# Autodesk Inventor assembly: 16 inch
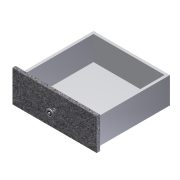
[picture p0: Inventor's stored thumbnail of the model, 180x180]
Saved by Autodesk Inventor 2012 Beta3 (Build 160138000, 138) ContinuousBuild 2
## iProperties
Created: 2011-02
Part Number: 16 inch
Document SubType Name: Assembly
Designer: Beta-8540w
Author: Beta-8540w
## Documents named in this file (12)
- C:\Inventor 2012 Essentials\Assemblies\Chapter 15\c15-04\c15-04-03.iam
- C:\Inventor 2012 Essentials\Parts\Chapter 15\c15-11.ipt
- C:\Inventor 2012 Essentials\Parts\Chapter 15\c15-12.ipt
- C:\Inventor 2012 Essentials\Parts\Chapter 15\c15-13.ipt
- C:\Inventor 2012 Essentials\Parts\Chapter 15\c15-15.ipt
- C:\Inventor 2012 Essentials\Parts\Chapter 15\c15-17.ipt
- C:\Inventor 2012 Essentials\Content Center Files\en-US\ANSI B18.6.3(28)\ANSI B18.6.3 - 8-36 UNF - 0.875(12).ipt
- C:\Inventor 2012 Essentials\Assemblies\Chapter 15\c15-04.iam
- C:\Inventor 2012 Essentials\Parts\Chapter 15\c15-11\c15-11-03.ipt
- C:\Inventor 2012 Essentials\Parts\Chapter 15\c15-12\c15-12-03.ipt
- C:\Inventor 2012 Essentials\Parts\Chapter 15\c15-13\c15-13-03.ipt
- C:\Inventor 2012 Essentials\Parts\Chapter 15\c15-15\c15-15-03.ipt
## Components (7 placed, 6 different names)
1. c15-11-03:1 — Mate:1, Flush:1, Mate:2, Mate:6, Mate:7, Knob Insert constraint, Knob Screw constraint, Mate:10, Mate:11
2. c15-12-03:1 — Flush:2, Mate:9, Flush:4, Flush:5, Flush:6
3. c15-13-03:1 — Mate:1, Flush:1, Mate:2, Flush:2, Mate:8, Mate:9, Flush:4, Flush:5
4. c15-13-03:2 — Flush:6, Mate:10, Mate:11
5. c15-15-03:1 — Mate:6, Mate:7, Mate:8
6. c15-17:1 — Knob Insert constraint
7. Cross Recessed Truss Head Machine Screw - Type IA - Inch No. 8 - 36 - 7/8:1 — Knob Screw constraint
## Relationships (15: Mate 8, Flush 5, Insert 2)
- Mate:1: c15-11-03:1 ↔ c15-13-03:1
- Flush:1: c15-11-03:1 ↔ c15-13-03:1
- Mate:2: c15-11-03:1 ↔ c15-13-03:1
- Flush:2: c15-12-03:1 ↔ c15-13-03:1
- Mate:6: c15-11-03:1 ↔ c15-15-03:1
- Mate:7: c15-11-03:1 ↔ c15-15-03:1
- Mate:8: c15-13-03:1 ↔ c15-15-03:1
- Mate:9: c15-12-03:1 ↔ c15-13-03:1
- Flush:4: c15-12-03:1 ↔ c15-13-03:1
- Flush:5: c15-12-03:1 ↔ c15-13-03:1
- Knob Insert constraint [Insert]: c15-11-03:1 ↔ c15-17:1
- Knob Screw constraint [Insert]: c15-11-03:1 ↔ Cross Recessed Truss Head Machine Screw - Type IA - Inch No. 8 - 36 - 7/8:1
- Flush:6: c15-12-03:1 ↔ c15-13-03:2
- Mate:10: c15-11-03:1 ↔ c15-13-03:2
- Mate:11: c15-11-03:1 ↔ c15-13-03:2
